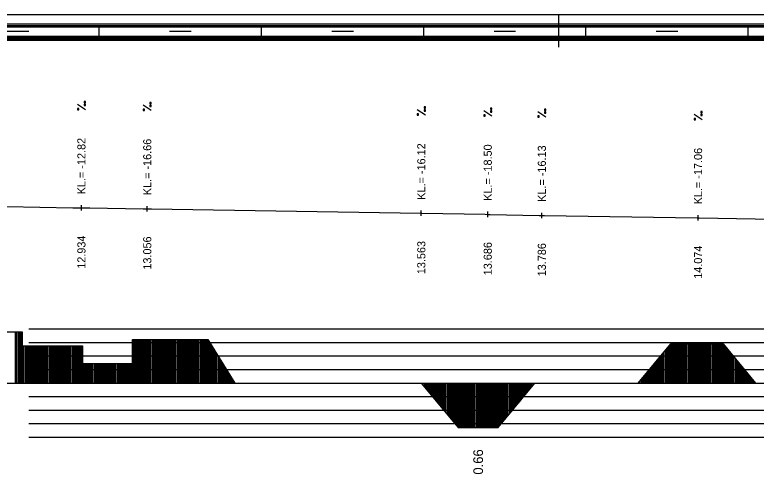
# Model space of a CAD drawing. Extents: x 2 to 10148, y 0 to 380.
# Drawn here: x 1579.4 to 1716.5, y 295.2 to 380 of the extents above; entities that cross this region are included whole.
import ezdxf

# ---------------------------------------------------------------- set-up
doc = ezdxf.new("R2010")
doc.units = 0
for name, color, linetype in [('NIVELETA_CARA', 7, 'Continuous'), ('NIVELETA_TEXT', 7, 'Continuous'), ('RAM', 7, 'Continuous'), ('ZRYCHL_CARA_C', 7, 'Continuous'), ('ZRYCHL_RASTR', 7, 'Continuous'), ('ZRYCHL_TEXT', 7, 'Continuous')]:
    doc.layers.add(name, color=color, linetype=linetype)

msp = doc.modelspace()

# ---------------------------------------------------------------- linework, layer by layer
at = {"layer": 'NIVELETA_CARA'}
for p, q in [((1577.95, 344.63), (1590.15, 344.38)), ((1590.15, 344.38), (1591.73, 344.35)), ((1591.73, 343.85), (1591.73, 344.85)), ((1591.73, 344.35), (1593.31, 344.33)), ((1593.31, 344.33), (1603.13, 344.2)), ((1603.13, 344.2), (1603.9, 344.19)), ((1603.9, 343.69), (1603.9, 344.69)), ((1603.9, 344.19), (1604.67, 344.18)), ((1604.67, 344.18), (1654.45, 343.35)), ((1654.45, 343.35), (1654.56, 343.35)), ((1654.56, 342.85), (1654.56, 343.85)), ((1654.56, 343.35), (1654.67, 343.35)), ((1654.67, 343.35), (1666.36, 343.16)), ((1666.36, 343.16), (1666.84, 343.15)), ((1666.84, 342.65), (1666.84, 343.65)), ((1666.84, 343.15), (1667.31, 343.14)), ((1667.31, 343.14), (1676.37, 342.97)), ((1676.37, 342.97), (1676.84, 342.96)), ((1676.84, 342.46), (1676.84, 343.46)), ((1676.84, 342.96), (1677.31, 342.96)), ((1677.31, 342.96), (1705.54, 342.5)), ((1705.72, 342), (1705.72, 343)), ((1705.54, 342.5), (1705.72, 342.5)), ((1705.72, 342.5), (1705.91, 342.5)), ((1705.91, 342.5), (1786.35, 341.12))]:
    msp.add_line(p, q, dxfattribs=at)
at = {"layer": 'NIVELETA_TEXT'}
for p, q in [((1592.48, 362.47), (1590.98, 363.47)), ((1592.48, 363.99), (1592.23, 363.99)), ((1592.23, 363.99), (1592.23, 363.75)), ((1592.23, 363.75), (1592.24, 363.74)), ((1592.23, 363.74), (1592.48, 363.74)), ((1592.48, 363.48), (1592.23, 363.48)), ((1592.23, 363.48), (1592.23, 363.24)), ((1592.23, 363.24), (1592.24, 363.23)), ((1592.23, 363.23), (1592.48, 363.23)), ((1592.48, 363.74), (1592.48, 363.99)), ((1592.48, 363.23), (1592.48, 363.48)), ((1604.64, 362.32), (1603.15, 363.31)), ((1604.65, 363.84), (1604.4, 363.84)), ((1604.4, 363.84), (1604.4, 363.59)), ((1604.4, 363.59), (1604.65, 363.59)), ((1604.4, 363.59), (1604.4, 363.59)), ((1604.65, 363.32), (1604.4, 363.32)), ((1604.4, 363.32), (1604.4, 363.08)), ((1604.65, 363.59), (1604.65, 363.84)), ((1604.65, 363.08), (1604.65, 363.32)), ((1591.23, 362.72), (1590.98, 362.72)), ((1590.98, 362.72), (1590.98, 362.48)), ((1590.98, 362.48), (1590.99, 362.47)), ((1590.98, 362.47), (1591.23, 362.47)), ((1591.23, 362.47), (1591.23, 362.72)), ((1603.4, 362.57), (1603.15, 362.57)), ((1603.15, 362.57), (1603.15, 362.32)), ((1603.15, 362.32), (1603.4, 362.32)), ((1603.15, 362.32), (1603.16, 362.32)), ((1603.4, 362.32), (1603.4, 362.57)), ((1604.4, 363.08), (1604.65, 363.08)), ((1604.4, 363.08), (1604.4, 363.08)), ((1655.31, 361.47), (1653.81, 362.47)), ((1655.31, 362.99), (1655.06, 362.99)), ((1655.06, 362.99), (1655.06, 362.75)), ((1655.06, 362.75), (1655.07, 362.74)), ((1655.06, 362.74), (1655.31, 362.74)), ((1655.31, 362.48), (1655.06, 362.48)), ((1655.06, 362.48), (1655.06, 362.24)), ((1655.06, 362.24), (1655.07, 362.23)), ((1655.06, 362.23), (1655.31, 362.23)), ((1655.31, 362.74), (1655.31, 362.99)), ((1655.31, 362.23), (1655.31, 362.48)), ((1667.58, 361.28), (1666.09, 362.27)), ((1667.59, 362.79), (1667.34, 362.79)), ((1667.34, 362.79), (1667.34, 362.55)), ((1667.34, 362.55), (1667.59, 362.55)), ((1667.34, 362.55), (1667.34, 362.55)), ((1667.59, 362.28), (1667.34, 362.28)), ((1667.34, 362.28), (1667.34, 362.04)), ((1667.34, 362.04), (1667.34, 362.03)), ((1667.34, 362.03), (1667.59, 362.03)), ((1667.59, 362.55), (1667.59, 362.79)), ((1667.59, 362.03), (1667.59, 362.28)), ((1677.59, 361.09), (1676.09, 362.08)), ((1677.59, 362.61), (1677.34, 362.61)), ((1677.34, 362.61), (1677.34, 362.37)), ((1677.34, 362.37), (1677.34, 362.36)), ((1677.34, 362.36), (1677.59, 362.36)), ((1677.59, 362.1), (1677.34, 362.1)), ((1677.34, 362.1), (1677.34, 361.85)), ((1677.34, 361.85), (1677.59, 361.85)), ((1677.34, 361.85), (1677.34, 361.85)), ((1677.59, 362.36), (1677.59, 362.61)), ((1677.59, 361.85), (1677.59, 362.1)), ((1706.47, 362.14), (1706.22, 362.14)), ((1706.22, 362.14), (1706.22, 361.9)), ((1706.22, 361.9), (1706.23, 361.89)), ((1706.22, 361.89), (1706.47, 361.89)), ((1706.47, 361.89), (1706.47, 362.14)), ((1654.06, 361.72), (1653.81, 361.72)), ((1653.81, 361.72), (1653.81, 361.48)), ((1653.81, 361.48), (1653.82, 361.47)), ((1653.81, 361.47), (1654.06, 361.47)), ((1654.06, 361.47), (1654.06, 361.72)), ((1666.34, 361.52), (1666.09, 361.52)), ((1666.09, 361.52), (1666.09, 361.28)), ((1666.09, 361.28), (1666.34, 361.28)), ((1666.09, 361.28), (1666.1, 361.28)), ((1666.34, 361.28), (1666.34, 361.52)), ((1676.34, 361.34), (1676.09, 361.34)), ((1676.09, 361.34), (1676.09, 361.1)), ((1676.09, 361.1), (1676.1, 361.09)), ((1676.09, 361.09), (1676.34, 361.09)), ((1676.34, 361.09), (1676.34, 361.34)), ((1706.47, 360.63), (1704.98, 361.62)), ((1705.22, 360.87), (1704.98, 360.87)), ((1704.98, 360.87), (1704.98, 360.63)), ((1704.98, 360.63), (1705.22, 360.63)), ((1704.98, 360.63), (1704.98, 360.63)), ((1705.22, 360.63), (1705.22, 360.87)), ((1706.47, 361.63), (1706.22, 361.63)), ((1706.22, 361.63), (1706.22, 361.39)), ((1706.22, 361.39), (1706.23, 361.38)), ((1706.22, 361.38), (1706.47, 361.38)), ((1706.47, 361.38), (1706.47, 361.63))]:
    msp.add_line(p, q, dxfattribs=at)
at = {"layer": 'RAM'}
for p, q in [((1850.83, 380), (1245.39, 380)), ((1680, 374), (1680, 380)), ((1850.83, 378.25), (1245.39, 378.25)), ((1850.83, 378), (1245.39, 378)), ((1850.83, 377.75), (1245.39, 377.75)), ((1578, 377), (1582, 377)), ((1595, 376), (1595, 378)), ((1608, 377), (1612, 377)), ((1625, 376), (1625, 378)), ((1638, 377), (1642, 377)), ((1655, 376), (1655, 378)), ((1668, 377), (1672, 377)), ((1685, 376), (1685, 378)), ((1698, 377), (1702, 377)), ((1715, 376), (1715, 378)), ((1850.83, 376), (1245.39, 376)), ((1850.83, 375.75), (1245.39, 375.75)), ((1850.83, 375.5), (1245.39, 375.5)), ((1850.83, 375.25), (1245.39, 375.25))]:
    msp.add_line(p, q, dxfattribs=at)
at = {"layer": 'ZRYCHL_CARA_C'}
for p, q in [((1570.07, 321.45), (1580.8, 321.45)), ((1579.57, 312), (1579.57, 321.45)), ((1579.82, 312), (1579.82, 321.45)), ((1580.07, 312), (1580.07, 321.45)), ((1580.32, 312), (1580.32, 321.45)), ((1580.57, 312), (1580.57, 321.45)), ((1580.8, 321.45), (1580.8, 318.85)), ((1601.15, 312), (1601.15, 320.03)), ((1601.15, 315.61), (1601.15, 320.03)), ((1601.15, 320.03), (1615.1, 320.03)), ((1601.4, 312), (1601.4, 320.03)), ((1601.65, 312), (1601.65, 320.03)), ((1601.9, 312), (1601.9, 320.03)), ((1602.15, 312), (1602.15, 320.03)), ((1602.4, 312), (1602.4, 320.03)), ((1602.65, 312), (1602.65, 320.03)), ((1602.9, 312), (1602.9, 320.03)), ((1603.15, 312), (1603.15, 320.03)), ((1603.4, 312), (1603.4, 320.03)), ((1603.65, 312), (1603.65, 320.03)), ((1603.9, 312), (1603.9, 320.03)), ((1604.15, 312), (1604.15, 320.03)), ((1604.4, 312), (1604.4, 320.03)), ((1604.65, 312), (1604.65, 320.03)), ((1604.9, 312), (1604.9, 320.03)), ((1605.15, 312), (1605.15, 320.03)), ((1605.4, 312), (1605.4, 320.03)), ((1605.65, 312), (1605.65, 320.03)), ((1605.9, 312), (1605.9, 320.03)), ((1606.15, 312), (1606.15, 320.03)), ((1606.4, 312), (1606.4, 320.03)), ((1606.65, 312), (1606.65, 320.03)), ((1606.9, 312), (1606.9, 320.03)), ((1607.15, 312), (1607.15, 320.03)), ((1607.4, 312), (1607.4, 320.03)), ((1607.65, 312), (1607.65, 320.03)), ((1607.9, 312), (1607.9, 320.03)), ((1608.15, 312), (1608.15, 320.03)), ((1608.4, 312), (1608.4, 320.03)), ((1608.65, 312), (1608.65, 320.03)), ((1608.9, 312), (1608.9, 320.03)), ((1609.15, 312), (1609.15, 320.03)), ((1609.4, 312), (1609.4, 320.03)), ((1609.65, 312), (1609.65, 320.03)), ((1609.9, 312), (1609.9, 320.03)), ((1610.15, 312), (1610.15, 320.03)), ((1610.4, 312), (1610.4, 320.03)), ((1610.65, 312), (1610.65, 320.03)), ((1610.9, 312), (1610.9, 320.03)), ((1611.15, 312), (1611.15, 320.03)), ((1611.4, 312), (1611.4, 320.03)), ((1611.65, 312), (1611.65, 320.03)), ((1611.9, 312), (1611.9, 320.03)), ((1612.15, 312), (1612.15, 320.03)), ((1612.4, 312), (1612.4, 320.03)), ((1612.65, 312), (1612.65, 320.03)), ((1612.9, 312), (1612.9, 320.03)), ((1613.15, 312), (1613.15, 320.03)), ((1613.4, 312), (1613.4, 320.03)), ((1613.65, 312), (1613.65, 320.03)), ((1613.9, 312), (1613.9, 320.03)), ((1614.15, 312), (1614.15, 320.03)), ((1614.4, 312), (1614.4, 320.03)), ((1614.65, 312), (1614.65, 320.03)), ((1614.9, 312), (1614.9, 320.03)), ((1615.1, 312), (1615.1, 320.03)), ((1615.1, 320.03), (1620.1, 312)), ((1615.35, 312), (1615.35, 319.63)), ((1580.8, 312), (1580.8, 318.85)), ((1580.8, 318.85), (1591.93, 318.85)), ((1581.05, 312), (1581.05, 318.85)), ((1581.3, 312), (1581.3, 318.85)), ((1581.55, 312), (1581.55, 318.85)), ((1581.8, 312), (1581.8, 318.85)), ((1582.05, 312), (1582.05, 318.85)), ((1582.3, 312), (1582.3, 318.85)), ((1582.55, 312), (1582.55, 318.85)), ((1582.8, 312), (1582.8, 318.85)), ((1583.05, 312), (1583.05, 318.85)), ((1583.3, 312), (1583.3, 318.85)), ((1583.55, 312), (1583.55, 318.85)), ((1583.8, 312), (1583.8, 318.85)), ((1584.05, 312), (1584.05, 318.85)), ((1584.3, 312), (1584.3, 318.85)), ((1584.55, 312), (1584.55, 318.85)), ((1584.8, 312), (1584.8, 318.85)), ((1585.05, 312), (1585.05, 318.85)), ((1585.3, 312), (1585.3, 318.85)), ((1585.55, 312), (1585.55, 318.85)), ((1585.8, 312), (1585.8, 318.85)), ((1586.05, 312), (1586.05, 318.85)), ((1586.3, 312), (1586.3, 318.85)), ((1586.55, 312), (1586.55, 318.85)), ((1586.8, 312), (1586.8, 318.85)), ((1587.05, 312), (1587.05, 318.85)), ((1587.3, 312), (1587.3, 318.85)), ((1587.55, 312), (1587.55, 318.85)), ((1587.8, 312), (1587.8, 318.85)), ((1588.05, 312), (1588.05, 318.85)), ((1588.3, 312), (1588.3, 318.85)), ((1588.55, 312), (1588.55, 318.85)), ((1588.8, 312), (1588.8, 318.85)), ((1589.05, 312), (1589.05, 318.85)), ((1589.3, 312), (1589.3, 318.85)), ((1589.55, 312), (1589.55, 318.85)), ((1589.8, 312), (1589.8, 318.85)), ((1590.05, 312), (1590.05, 318.85)), ((1590.3, 312), (1590.3, 318.85)), ((1590.55, 312), (1590.55, 318.85)), ((1590.8, 312), (1590.8, 318.85)), ((1591.05, 312), (1591.05, 318.85)), ((1591.3, 312), (1591.3, 318.85)), ((1591.55, 312), (1591.55, 318.85)), ((1591.8, 312), (1591.8, 318.85)), ((1591.93, 318.85), (1591.93, 315.61)), ((1615.6, 312), (1615.6, 319.23)), ((1615.85, 312), (1615.85, 318.83)), ((1616.1, 312), (1616.1, 318.43)), ((1616.35, 312), (1616.35, 318.03)), ((1694.67, 312), (1700.67, 319.22)), ((1699.67, 312), (1699.67, 318.01)), ((1699.92, 312), (1699.92, 318.31)), ((1700.17, 312), (1700.17, 318.62)), ((1700.42, 312), (1700.42, 318.92)), ((1700.67, 312), (1700.67, 319.22)), ((1700.67, 319.22), (1710.36, 319.22)), ((1700.92, 312), (1700.92, 319.22)), ((1701.17, 312), (1701.17, 319.22)), ((1701.42, 312), (1701.42, 319.22)), ((1701.67, 312), (1701.67, 319.22)), ((1701.92, 312), (1701.92, 319.22)), ((1702.17, 312), (1702.17, 319.22)), ((1702.42, 312), (1702.42, 319.22)), ((1702.67, 312), (1702.67, 319.22)), ((1702.92, 312), (1702.92, 319.22)), ((1703.17, 312), (1703.17, 319.22)), ((1703.42, 312), (1703.42, 319.22)), ((1703.67, 312), (1703.67, 319.22)), ((1703.92, 312), (1703.92, 319.22)), ((1704.17, 312), (1704.17, 319.22)), ((1704.42, 312), (1704.42, 319.22)), ((1704.67, 312), (1704.67, 319.22)), ((1704.92, 312), (1704.92, 319.22)), ((1705.17, 312), (1705.17, 319.22)), ((1705.42, 312), (1705.42, 319.22)), ((1705.67, 312), (1705.67, 319.22)), ((1705.92, 312), (1705.92, 319.22)), ((1706.17, 312), (1706.17, 319.22)), ((1706.42, 312), (1706.42, 319.22)), ((1706.67, 312), (1706.67, 319.22)), ((1706.92, 312), (1706.92, 319.22)), ((1707.17, 312), (1707.17, 319.22)), ((1707.42, 312), (1707.42, 319.22)), ((1707.67, 312), (1707.67, 319.22)), ((1707.92, 312), (1707.92, 319.22)), ((1708.17, 312), (1708.17, 319.22)), ((1708.42, 312), (1708.42, 319.22)), ((1708.67, 312), (1708.67, 319.22)), ((1708.92, 312), (1708.92, 319.22)), ((1709.17, 312), (1709.17, 319.22)), ((1709.42, 312), (1709.42, 319.22)), ((1709.67, 312), (1709.67, 319.22)), ((1709.92, 312), (1709.92, 319.22)), ((1710.17, 312), (1710.17, 319.22)), ((1710.36, 312), (1710.36, 319.22)), ((1710.36, 319.22), (1716.36, 312)), ((1710.61, 312), (1710.61, 318.92)), ((1710.86, 312), (1710.86, 318.62)), ((1711.11, 312), (1711.11, 318.31)), ((1711.36, 312), (1711.36, 318.01)), ((1616.6, 312), (1616.6, 317.62)), ((1616.85, 312), (1616.85, 317.22)), ((1617.1, 312), (1617.1, 316.82)), ((1698.67, 312), (1698.67, 316.81)), ((1698.92, 312), (1698.92, 317.11)), ((1699.17, 312), (1699.17, 317.41)), ((1699.42, 312), (1699.42, 317.71)), ((1711.61, 312), (1711.61, 317.71)), ((1711.86, 312), (1711.86, 317.41)), ((1712.11, 312), (1712.11, 317.11)), ((1712.36, 312), (1712.36, 316.81)), ((1591.93, 312), (1591.93, 315.61)), ((1591.93, 315.61), (1601.15, 315.61)), ((1592.18, 312), (1592.18, 315.61)), ((1592.43, 312), (1592.43, 315.61)), ((1592.68, 312), (1592.68, 315.61)), ((1592.93, 312), (1592.93, 315.61)), ((1593.18, 312), (1593.18, 315.61)), ((1593.43, 312), (1593.43, 315.61)), ((1593.68, 312), (1593.68, 315.61)), ((1593.93, 312), (1593.93, 315.61)), ((1594.18, 312), (1594.18, 315.61)), ((1594.43, 312), (1594.43, 315.61)), ((1594.68, 312), (1594.68, 315.61)), ((1594.93, 312), (1594.93, 315.61)), ((1595.18, 312), (1595.18, 315.61)), ((1595.43, 312), (1595.43, 315.61)), ((1595.68, 312), (1595.68, 315.61)), ((1595.93, 312), (1595.93, 315.61)), ((1596.18, 312), (1596.18, 315.61)), ((1596.43, 312), (1596.43, 315.61)), ((1596.68, 312), (1596.68, 315.61)), ((1596.93, 312), (1596.93, 315.61)), ((1597.18, 312), (1597.18, 315.61)), ((1597.43, 312), (1597.43, 315.61)), ((1597.68, 312), (1597.68, 315.61)), ((1597.93, 312), (1597.93, 315.61)), ((1598.18, 312), (1598.18, 315.61)), ((1598.43, 312), (1598.43, 315.61)), ((1598.68, 312), (1598.68, 315.61)), ((1598.93, 312), (1598.93, 315.61)), ((1599.18, 312), (1599.18, 315.61)), ((1599.43, 312), (1599.43, 315.61)), ((1599.68, 312), (1599.68, 315.61)), ((1599.93, 312), (1599.93, 315.61)), ((1600.18, 312), (1600.18, 315.61)), ((1600.43, 312), (1600.43, 315.61)), ((1600.68, 312), (1600.68, 315.61)), ((1600.93, 312), (1600.93, 315.61)), ((1617.35, 312), (1617.35, 316.42)), ((1617.6, 312), (1617.6, 316.02)), ((1617.85, 312), (1617.85, 315.62)), ((1618.1, 312), (1618.1, 315.21)), ((1697.42, 312), (1697.42, 315.31)), ((1697.67, 312), (1697.67, 315.61)), ((1697.92, 312), (1697.92, 315.91)), ((1698.17, 312), (1698.17, 316.21)), ((1698.42, 312), (1698.42, 316.51)), ((1712.61, 312), (1712.61, 316.51)), ((1712.86, 312), (1712.86, 316.21)), ((1713.11, 312), (1713.11, 315.91)), ((1713.36, 312), (1713.36, 315.61)), ((1713.61, 312), (1713.61, 315.31)), ((1618.35, 312), (1618.35, 314.81)), ((1618.6, 312), (1618.6, 314.41)), ((1618.85, 312), (1618.85, 314.01)), ((1696.42, 312), (1696.42, 314.1)), ((1696.67, 312), (1696.67, 314.41)), ((1696.92, 312), (1696.92, 314.71)), ((1697.17, 312), (1697.17, 315.01)), ((1713.86, 312), (1713.86, 315.01)), ((1714.11, 312), (1714.11, 314.71)), ((1714.36, 312), (1714.36, 314.41)), ((1714.61, 312), (1714.61, 314.1)), ((1619.1, 312), (1619.1, 313.61)), ((1619.35, 312), (1619.35, 313.21)), ((1619.6, 312), (1619.6, 312.8)), ((1695.17, 312), (1695.17, 312.6)), ((1695.42, 312), (1695.42, 312.9)), ((1695.67, 312), (1695.67, 313.2)), ((1695.92, 312), (1695.92, 313.5)), ((1696.17, 312), (1696.17, 313.8)), ((1714.86, 312), (1714.86, 313.8)), ((1715.11, 312), (1715.11, 313.5)), ((1715.36, 312), (1715.36, 313.2)), ((1715.61, 312), (1715.61, 312.9)), ((1715.86, 312), (1715.86, 312.6)), ((1245.39, 312), (1850.83, 312)), ((1619.85, 312), (1619.85, 312.4)), ((1620.1, 312), (1620.1, 312)), ((1654.56, 312), (1661.36, 303.78)), ((1654.81, 312), (1654.81, 311.7)), ((1655.06, 312), (1655.06, 311.4)), ((1655.31, 312), (1655.31, 311.09)), ((1655.56, 312), (1655.56, 310.79)), ((1655.81, 312), (1655.81, 310.49)), ((1656.06, 312), (1656.06, 310.19)), ((1656.31, 312), (1656.31, 309.88)), ((1656.56, 312), (1656.56, 309.58)), ((1656.81, 312), (1656.81, 309.28)), ((1657.06, 312), (1657.06, 308.98)), ((1657.31, 312), (1657.31, 308.67)), ((1657.56, 312), (1657.56, 308.37)), ((1657.81, 312), (1657.81, 308.07)), ((1658.06, 312), (1658.06, 307.77)), ((1658.31, 312), (1658.31, 307.46)), ((1658.56, 312), (1658.56, 307.16)), ((1658.81, 312), (1658.81, 306.86)), ((1659.06, 312), (1659.06, 306.56)), ((1659.31, 312), (1659.31, 306.26)), ((1659.56, 312), (1659.56, 305.95)), ((1659.81, 312), (1659.81, 305.65)), ((1660.06, 312), (1660.06, 305.35)), ((1660.31, 312), (1660.31, 305.05)), ((1660.56, 312), (1660.56, 304.74)), ((1660.81, 312), (1660.81, 304.44)), ((1661.06, 312), (1661.06, 304.14)), ((1661.31, 312), (1661.31, 303.84)), ((1661.36, 312), (1661.36, 303.78)), ((1661.61, 312), (1661.61, 303.78)), ((1661.86, 312), (1661.86, 303.78)), ((1662.11, 312), (1662.11, 303.78)), ((1662.36, 312), (1662.36, 303.78)), ((1662.61, 312), (1662.61, 303.78)), ((1662.86, 312), (1662.86, 303.78)), ((1663.11, 312), (1663.11, 303.78)), ((1663.36, 312), (1663.36, 303.78)), ((1663.61, 312), (1663.61, 303.78)), ((1663.86, 312), (1663.86, 303.78)), ((1664.11, 312), (1664.11, 303.78)), ((1664.36, 312), (1664.36, 303.78)), ((1664.61, 312), (1664.61, 303.78)), ((1664.86, 312), (1664.86, 303.78)), ((1665.11, 312), (1665.11, 303.78)), ((1665.36, 312), (1665.36, 303.78)), ((1665.61, 312), (1665.61, 303.78)), ((1665.86, 312), (1665.86, 303.78)), ((1666.11, 312), (1666.11, 303.78)), ((1666.36, 312), (1666.36, 303.78)), ((1666.61, 312), (1666.61, 303.78)), ((1666.86, 312), (1666.86, 303.78)), ((1667.11, 312), (1667.11, 303.78)), ((1667.36, 312), (1667.36, 303.78)), ((1667.61, 312), (1667.61, 303.78)), ((1667.86, 312), (1667.86, 303.78)), ((1668.11, 312), (1668.11, 303.78)), ((1668.36, 312), (1668.36, 303.78)), ((1668.61, 312), (1668.61, 303.78)), ((1668.77, 312), (1668.77, 303.78)), ((1668.77, 303.78), (1675.57, 312)), ((1669.02, 312), (1669.02, 304.08)), ((1669.27, 312), (1669.27, 304.38)), ((1669.52, 312), (1669.52, 304.68)), ((1669.77, 312), (1669.77, 304.99)), ((1670.02, 312), (1670.02, 305.29)), ((1670.27, 312), (1670.27, 305.59)), ((1670.52, 312), (1670.52, 305.89)), ((1670.77, 312), (1670.77, 306.19)), ((1671.02, 312), (1671.02, 306.5)), ((1671.27, 312), (1671.27, 306.8)), ((1671.52, 312), (1671.52, 307.1)), ((1671.77, 312), (1671.77, 307.4)), ((1672.02, 312), (1672.02, 307.71)), ((1672.27, 312), (1672.27, 308.01)), ((1672.52, 312), (1672.52, 308.31)), ((1672.77, 312), (1672.77, 308.61)), ((1673.02, 312), (1673.02, 308.92)), ((1673.27, 312), (1673.27, 309.22)), ((1673.52, 312), (1673.52, 309.52)), ((1673.77, 312), (1673.77, 309.82)), ((1674.02, 312), (1674.02, 310.13)), ((1674.27, 312), (1674.27, 310.43)), ((1674.52, 312), (1674.52, 310.73)), ((1674.77, 312), (1674.77, 311.03)), ((1675.02, 312), (1675.02, 311.33)), ((1675.27, 312), (1675.27, 311.64)), ((1675.52, 312), (1675.52, 311.94)), ((1694.92, 312), (1694.92, 312.3)), ((1716.11, 312), (1716.11, 312.3)), ((1661.36, 303.78), (1668.77, 303.78))]:
    msp.add_line(p, q, dxfattribs=at)
at = {"layer": 'ZRYCHL_RASTR'}
for p, q in [((1582, 322), (1778, 322)), ((1582, 319.5), (1778, 319.5)), ((1582, 317), (1778, 317)), ((1582, 314.5), (1778, 314.5)), ((1582, 309.5), (1778, 309.5)), ((1582, 307), (1778, 307)), ((1582, 304.5), (1778, 304.5)), ((1582, 302), (1778, 302))]:
    msp.add_line(p, q, dxfattribs=at)

# ---------------------------------------------------------------- texts
at = {"layer": 'NIVELETA_TEXT'}
for s, p in [('KL.= -12.82', (1592.48, 346.85)), ('KL.= -16.66', (1604.65, 346.69)), ('KL.= -16.12', (1655.31, 345.85)), ('KL.= -18.50', (1667.59, 345.65)), ('KL.= -16.13', (1677.59, 345.46)), ('KL.= -17.06', (1706.47, 345)), ('12.934', (1592.48, 333.1)), ('13.056', (1604.65, 332.94)), ('13.563', (1655.31, 332.1)), ('13.686', (1667.59, 331.9)), ('13.786', (1677.59, 331.71)), ('14.074', (1706.47, 331.25))]:
    msp.add_text(s, height=1.5, rotation=90, dxfattribs=at).set_placement(p)
at = {"layer": 'ZRYCHL_TEXT'}
msp.add_text('0.66', height=1.8, rotation=90, dxfattribs=at).set_placement((1665.97, 295.08))

doc.saveas('drawing.dxf')
